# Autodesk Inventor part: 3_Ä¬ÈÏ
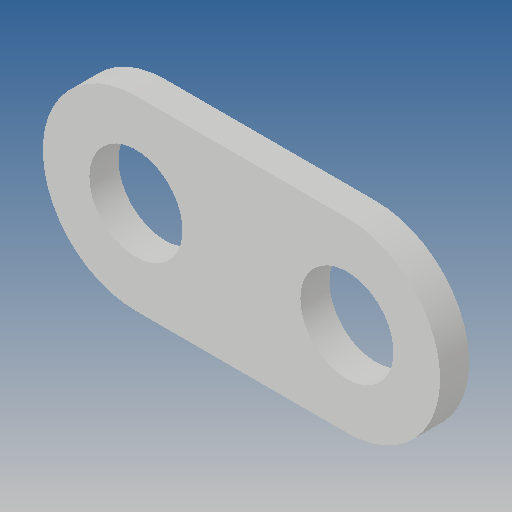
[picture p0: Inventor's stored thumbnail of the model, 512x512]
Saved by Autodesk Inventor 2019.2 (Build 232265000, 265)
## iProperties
Created: 2010-06
Part Number: 3_Ä¬ÈÏ
Material: Ogólny
Document SubType Name: Modeling
Designer: CADENGINEERING4
Density: 1 g/cm^3
Appearance: Domyślna
Author: CADENGINEERING4
Revision Number: ÈÎºÎ
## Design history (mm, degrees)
feature "NONE"
node "Bryła1"
